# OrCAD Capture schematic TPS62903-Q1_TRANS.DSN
size D; title: TPS62903-Q1 3-V to 18V, 3-A, Automotive Low IQ Buck Converter with +165°C TJ; rev: 1.0; note: Datasheet: SLVSG65     EVM: SNVU818; note: Synchronous Step Down Converter
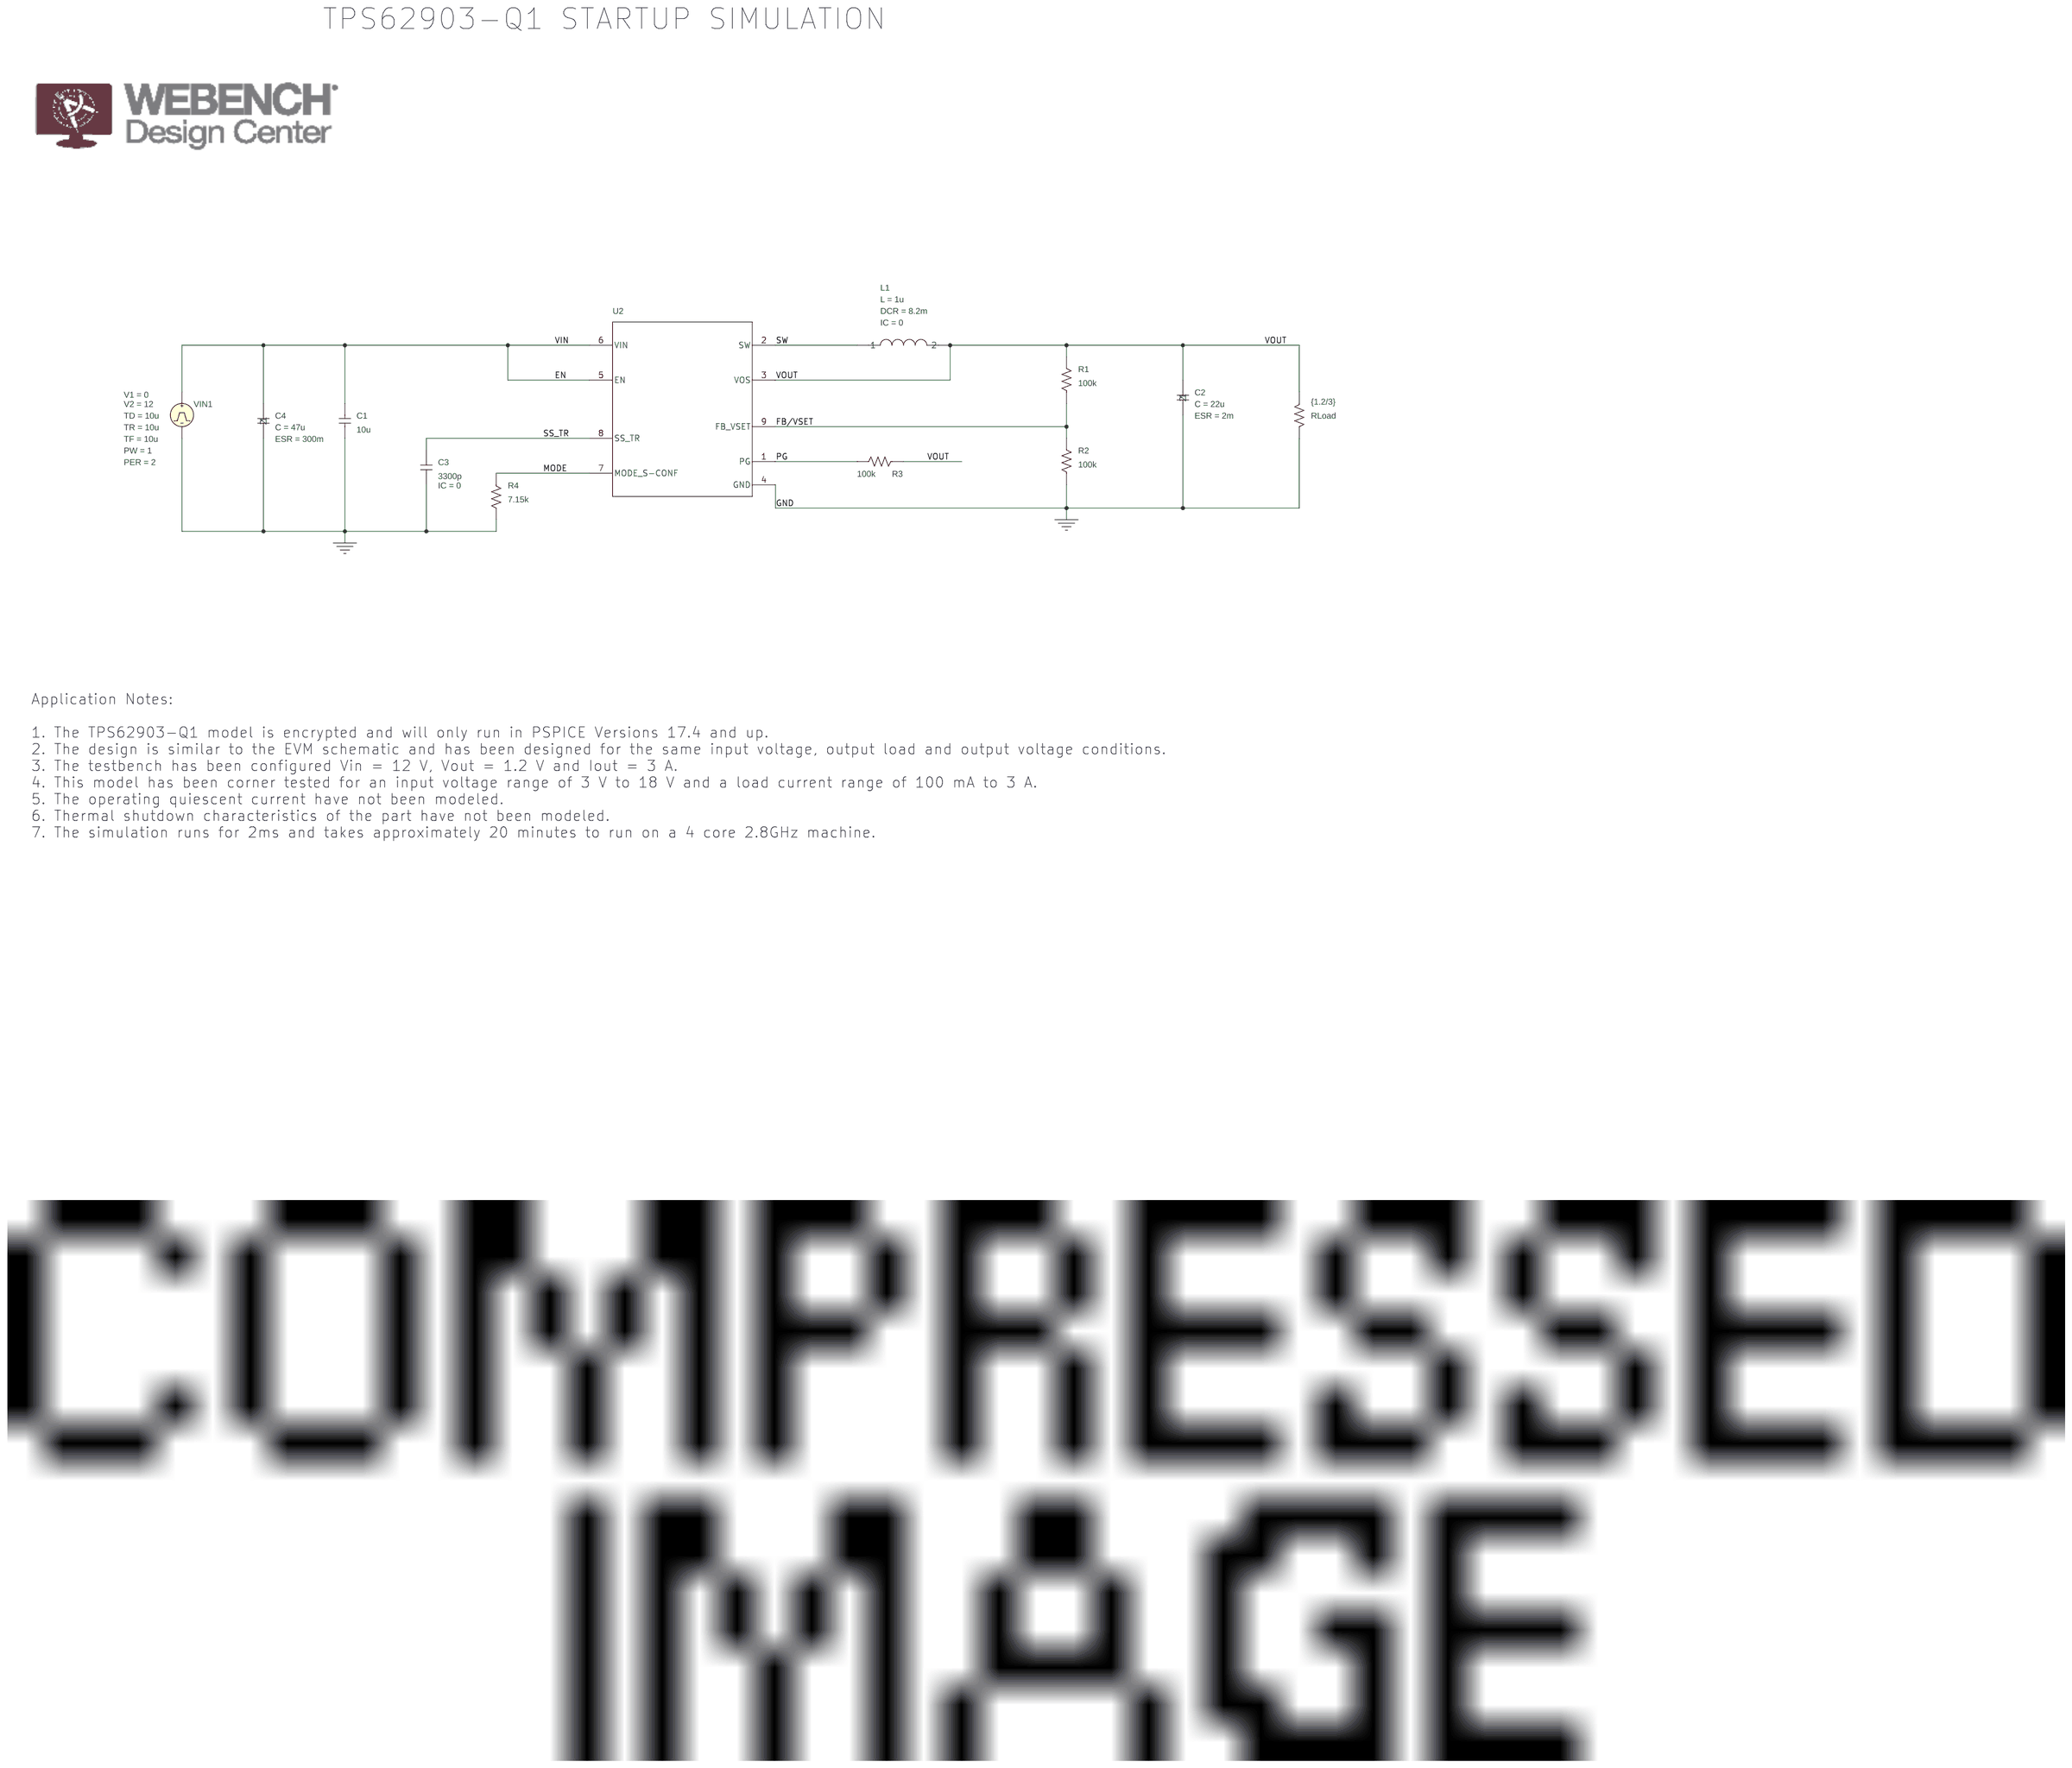
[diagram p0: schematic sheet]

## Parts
C1  10u  [RAD/CK05]
C2  CESR
C3  3300p  [RAD/CK05]
C4  CESR
L1  LDCR
R1  100k  [AX/RC05]
R2  100k  [AX/RC05]
R3  100k  [AX/RC05]
R4  7.15k  [AX/RC05]
RLoad  {1.2/3}  [AX/RC05]
U2  Value  [RYT0009A-MFG]
VIN1  VPULSE

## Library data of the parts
C1 = C
C2 = CESR: C: 22u; ESR: 2m; IC: 0; PSpiceTemplate: X^@REFDES %1 %2 @MODEL PARAMS: ?C|C=@C||C=10U| ?ESR|ESR=@ESR||ESR=2M| ?IC|IC=@IC||IC=1N| ?X|X=@X||X=1|; X: 1
C3 = C: IC: 0
C4 = CESR_1: C: 47u; ESR: 300m; IC: 0; PSpiceTemplate: X^@REFDES %1 %2 @MODEL PARAMS: ?C|C=@C||C=10U| ?ESR|ESR=@ESR||ESR=2M| ?IC|IC=@IC||IC=1N| ?X|X=@X||X=1|; X: 1
L1 = LDCR: DCR: 8.2m; IC: 0; L: 1u
R1-R4 RLoad = R
U2 = TPS62903-Q1RYT_TRANS: PSpiceTemplate: X^@REFDES  %EN %FB_VSET %GND %MODE_S-CONF %PG %SS_TR %SW %VIN %VOS @MODEL
VIN1 = VPULSE: PER: 2; PW: 1; TD: 10u; TF: 10u; TR: 10u; V1: 0; V2: 12

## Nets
0: C1.2 C2.2 C3.2 C4.2 R2.1 R4.2 RLoad.2 U2.4(GND) VIN1.2(-)
EN: C1.1 C4.1 U2.5(EN) U2.6(VIN) VIN1.1(+)
FB/VSET: R1.1 R2.2 U2.9(FB_VSET)
MODE: R4.1 U2.7(MODE_S-CONF)
PG: R3.2 U2.1(PG)
SS_TR: C3.1 U2.8(SS_TR)
SW: L1.1 U2.2(SW)
VOUT: C2.1 L1.2 R1.2 R3.1 RLoad.1 U2.3(VOS)

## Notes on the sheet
- TPS62903-Q1 STARTUP SIMULATION
- Application Notes:
  1. The TPS62903-Q1 model is encrypted and will only run in PSPICE Versions 17.4 and up.
  2. The design is similar to the EVM schematic and has been designed for the same input voltage, output load and output voltage conditions.
  3. The testbench has been configured Vin = 12 V, Vout = 1.2 V and Iout = 3 A.
  4. This model has been corner tested for an input voltage range of 3 V to 18 V and a load current range of 100 mA to 3 A.
  5. The operating quiescent current have not been modeled.
  6. Thermal shutdown characteristics of the part have not been modeled.
  7. The simulation runs for 2ms and takes approximately 20 minutes to run on a 4 core 2.8GHz machine.
